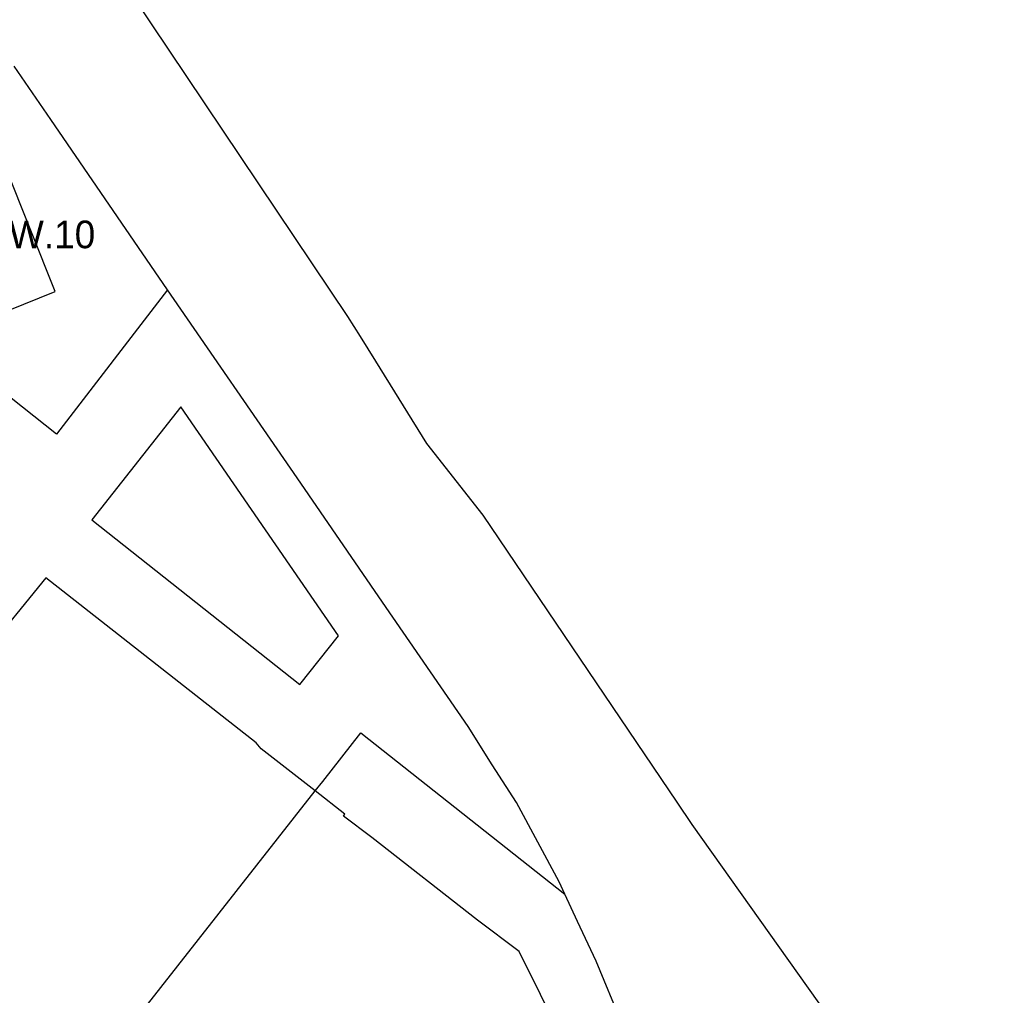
# Model space of a CAD drawing. Extents: x 7425067 to 7426806, y 5549054 to 5550619.
# Drawn here: x 7426359 to 7426536.4, y 5549951.6 to 5550128 of the extents above; entities that cross this region are included whole.
import ezdxf

# ---------------------------------------------------------------- set-up
doc = ezdxf.new("R2010")
doc.units = 0
for name, color, linetype in [('LIN_linia zabudowy obowiązująca', 7, 'Continuous'), ('LIN_linie_rozgraniczajace', 7, 'Continuous'), ('TXT_Oznaczenia_przeznaczen', 7, 'Continuous')]:
    doc.layers.add(name, color=color, linetype=linetype)

msp = doc.modelspace()

# ---------------------------------------------------------------- linework, layer by layer
at = {"layer": 'LIN_linia zabudowy obowiązująca'}
for points in [[(7426355.8072, 5550100.8957), (7426339.89, 5550094.44), (7426348.61, 5550072.94), (7426348.37, 5550072.84), (7426348.7, 5550072.03), (7426365.42, 5550078.82), (7426356.51, 5550101.18)], [(7426388.1475, 5550057.9273), (7426372.0171, 5550037.5198)], [(7426409.6146, 5550007.7425), (7426416.6405, 5550016.5372), (7426400.8829, 5550039.4198), (7426388.1475, 5550057.9273)], [(7426372.0171, 5550037.5198), (7426409.6146, 5550007.7425)], [(7426363.71, 5550027.01), (7426352.38, 5550013.17), (7426294.43, 5549939.36), (7426265.8603, 5549903.2149)], [(7426477.01, 5549895.39), (7426474.02, 5549897.65), (7426477.58, 5549902.29), (7426460.7502, 5549936.2646), (7426449.26, 5549959.46), (7426441.71, 5549965.17), (7426422.62, 5549980.1), (7426417.53, 5549983.98), (7426417.78, 5549984.29), (7426412.3933, 5549988.5089), (7426402.65, 5549996.14), (7426401.75, 5549997.21), (7426363.71, 5550027.01)]]:
    msp.add_lwpolyline(points, dxfattribs=at)
at = {"layer": 'LIN_linie_rozgraniczajace'}
for points in [[(7426376.27, 5550136.98), (7426418.26, 5550074.28)], [(7426364.6399, 5550109.8702), (7426358.0227, 5550119.5325)], [(7426385.71, 5550079.11), (7426364.6399, 5550109.8702)], [(7426385.71, 5550079.11), (7426365.64, 5550053)], [(7426409.12, 5550045.09), (7426385.71, 5550079.11)], [(7426418.26, 5550074.28), (7426420.5271, 5550070.6508)], [(7426420.5271, 5550070.6508), (7426423.32, 5550066.18)], [(7426365.64, 5550053), (7426345.1, 5550069.3)], [(7426423.32, 5550066.18), (7426432.5, 5550051.32)], [(7426432.5, 5550051.32), (7426442.696, 5550038.3784)], [(7426424.59, 5550022.625), (7426409.12, 5550045.09)], [(7426442.696, 5550038.3784), (7426477.7715, 5549986.4738)], [(7426440.06, 5550000.16), (7426424.59, 5550022.625)], [(7426444.395, 5549993.23), (7426440.06, 5550000.16)], [(7426413.76, 5549990.25), (7426420.6258, 5549998.9969)], [(7426420.6258, 5549998.9969), (7426457.5109, 5549969.8668)], [(7426448.76, 5549986.41), (7426444.395, 5549993.23)], [(7426359.67, 5549921.34), (7426412.3933, 5549988.5089), (7426413.76, 5549990.25)], [(7426456.47, 5549972.08), (7426448.76, 5549986.41)], [(7426477.7715, 5549986.4738), (7426480.4904, 5549982.4504)], [(7426480.4904, 5549982.4504), (7426536.4027, 5549903.6836)], [(7426457.5109, 5549969.8668), (7426456.47, 5549972.08)], [(7426459.835, 5549964.925), (7426457.5109, 5549969.8668)], [(7426463.2, 5549957.77), (7426459.835, 5549964.925)], [(7426467.83, 5549946.55), (7426463.2, 5549957.77)]]:
    msp.add_lwpolyline(points, dxfattribs=at)

# ---------------------------------------------------------------- texts
at = {"layer": 'TXT_Oznaczenia_przeznaczen'}
msp.add_text('MW.10', height=5, dxfattribs=at).set_placement((7426351.4853, 5550086.6179))

doc.saveas('drawing.dxf')
